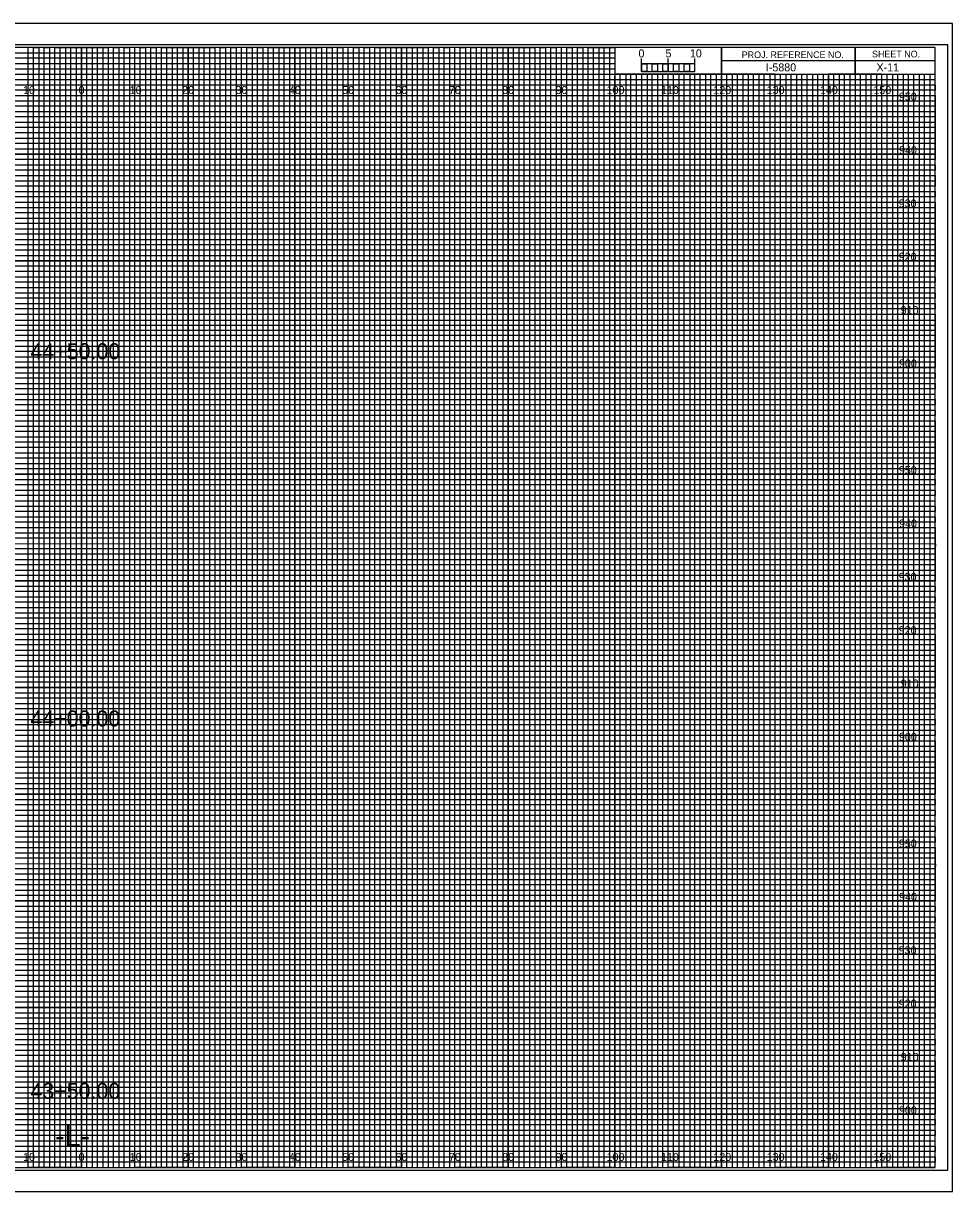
# Model space of a CAD drawing. Extents: x -13 to 323, y -4 to 3074.
# Drawn here: x 149.1 to 323.3, y 1975.5 to 2194.5 of the extents above; entities that cross this region are included whole.
import ezdxf

# ---------------------------------------------------------------- set-up
doc = ezdxf.new("R2010")
doc.units = 0
for name, color, linetype in [('Prop XS Alignment Label', 7, 'Continuous'), ('Prop XS Bar Scale Labels', 7, 'Continuous'), ('Prop XS Elevation Labels', 7, 'Continuous'), ('Prop XS Offset Labels', 7, 'Continuous'), ('Prop XS Project Number', 7, 'Continuous'), ('Prop XS Sheet Number', 7, 'Continuous'), ('Prop XS Station Labels', 7, 'Continuous'), ('Sheet Cross Section CELL', 7, 'Continuous'), ('Sheet Cross Section Grid Major CELL', 7, 'Continuous'), ('Sheet Cross Section Grid Middle CELL', 7, 'Continuous'), ('Sheet Cross Section Grid Minor 1 CELL', 7, 'Continuous'), ('Sheet Cross Section Grid Minor 2 CELL', 7, 'Continuous'), ('Sheet Cross Section Scale CELL', 7, 'Continuous'), ('Sheet Cutting Line CELL', 7, 'Continuous'), ('Sheet DOT Grid CELL', 7, 'Continuous'), ('Sheet Plot Border Inside CELL', 7, 'Continuous'), ('Sheet Plot Border Outside CELL', 7, 'Continuous')]:
    doc.layers.add(name, color=color, linetype=linetype)

msp = doc.modelspace()

# ---------------------------------------------------------------- linework, layer by layer
at = {"layer": 'Sheet Cross Section CELL'}
for p, q in [((305, 2190), (305, 2185)), ((305, 2185), (305, 2190)), ((280, 2187.5), (280, 2185)), ((320, 2187.49), (280, 2187.49)), ((280, 2185), (320, 2185))]:
    msp.add_line(p, q, dxfattribs=at)
for points in [[(320, 2190), (0, 2190), (0, 1980), (320, 1980)], [(280, 2190), (260, 2190), (260, 2185.03), (280, 2185.03)], [(320, 2190), (280, 2190), (280, 2185), (320, 2185)]]:
    msp.add_lwpolyline(points, close=True, dxfattribs=at)
at = {"layer": 'Sheet Cross Section Grid Major CELL'}
for p, q in [((150, 2190), (140, 2190)), ((150, 1980), (150, 2190)), ((170, 2190), (160, 2190)), ((160, 2190), (160, 1980)), ((170, 1980), (170, 2190)), ((190, 2190), (180, 2190)), ((180, 2190), (180, 1980)), ((190, 1980), (190, 2190)), ((210, 2190), (200, 2190)), ((200, 2190), (200, 1980)), ((210, 1980), (210, 2190)), ((230, 2190), (220, 2190)), ((220, 2190), (220, 1980)), ((230, 1980), (230, 2190)), ((250, 2190), (240, 2190)), ((240, 2190), (240, 1980)), ((250, 1980), (250, 2190)), ((260, 2190), (260, 1980)), ((270, 1980), (270, 2185)), ((290, 2185), (280, 2185)), ((280, 2185), (280, 1980)), ((290, 1980), (290, 2185)), ((310, 2185), (300, 2185)), ((300, 2185), (300, 1980)), ((310, 1980), (310, 2185)), ((160, 1980), (150, 1980)), ((180, 1980), (170, 1980)), ((200, 1980), (190, 1980)), ((220, 1980), (210, 1980)), ((240, 1980), (230, 1980)), ((260, 1980), (250, 1980)), ((280, 1980), (270, 1980)), ((300, 1980), (290, 1980)), ((320, 1980), (310, 1980)), ((320, 1980), (320, 1980))]:
    msp.add_line(p, q, dxfattribs=at)
for points in [[(0, 2180), (320, 2180), (320, 2170), (0, 2170)], [(0, 2160), (320, 2160), (320, 2150), (0, 2150)], [(0, 2140), (320, 2140), (320, 2130), (0, 2130)], [(0, 2120), (320, 2120), (320, 2110), (0, 2110)], [(0, 2100), (320, 2100), (320, 2090), (0, 2090)], [(0, 2080), (320, 2080), (320, 2070), (0, 2070)], [(0, 2060), (320, 2060), (320, 2050), (0, 2050)], [(0, 2040), (320, 2040), (320, 2030), (0, 2030)], [(0, 2020), (320, 2020), (320, 2010), (0, 2010)], [(0, 2000), (320, 2000), (320, 1990), (0, 1990)]]:
    msp.add_lwpolyline(points, dxfattribs=at)
at = {"layer": 'Sheet Cross Section Grid Middle CELL'}
for points in [[(145, 1980), (155, 1980), (155, 2190), (165, 2190), (165, 1980), (175, 1980), (175, 2190), (185, 2190), (185, 1980), (195, 1980), (195, 2190), (205, 2190), (205, 1980), (215, 1980), (215, 2190), (225, 2190), (225, 1980), (235, 1980), (235, 2190), (245, 2190), (245, 1980), (255, 1980), (255, 2190), (259.93, 2190), (260, 2190), (260, 2185), (264.99, 2185), (264.99, 1980), (275, 1980), (275, 2185), (285, 2185), (285, 1980), (295, 1980), (295, 2185), (305, 2185), (305, 1980), (315, 1980), (315, 2185)], [(0, 2185), (275, 2185)], [(0, 2165), (320, 2165), (320, 2175), (0, 2175)], [(0, 2145), (320, 2145), (320, 2155), (0, 2155)], [(0, 2125), (320, 2125), (320, 2135), (0, 2135)], [(0, 2105), (320, 2105), (320, 2115), (0, 2115)], [(0, 2085), (320, 2085), (320, 2095), (0, 2095)], [(0, 2065), (320, 2065), (320, 2075), (0, 2075)], [(0, 2045), (320, 2045), (320, 2055), (0, 2055)], [(0, 2025), (320, 2025), (320, 2035), (0, 2035)], [(0, 2005), (320, 2005), (320, 2015), (0, 2015)], [(0, 1985), (320, 1985), (320, 1995), (0, 1995)]]:
    msp.add_lwpolyline(points, dxfattribs=at)
at = {"layer": 'Sheet Cross Section Grid Minor 1 CELL'}
for p, q in [((0, 2189), (260, 2189)), ((260, 2187.98), (0, 2187.98)), ((260, 2189), (260, 2187.98)), ((0, 2187), (260, 2187)), ((260, 2185.89), (0, 2185.89)), ((260, 2187), (260, 2185.89)), ((0, 2184), (320, 2184))]:
    msp.add_line(p, q, dxfattribs=at)
for points in [[(0, 2183), (270, 2183), (320, 2183), (320, 2182), (0, 2182)], [(0, 2181), (320, 2181), (320, 2179), (0, 2179)], [(0, 2178), (320, 2178), (320, 2177), (0, 2176.98)], [(0, 2176), (320, 2176), (320, 2174), (0, 2174)], [(0, 2173), (320, 2173), (320, 2172), (0, 2172)], [(0, 2171), (320, 2171), (320, 2169), (0, 2169)], [(0, 2168), (320, 2168), (320, 2167), (0, 2167)], [(0, 2166), (320, 2166), (320, 2164), (0, 2164)], [(0, 2163), (320, 2163), (320, 2162), (0, 2162)], [(0, 2161), (320, 2161), (320, 2159), (0, 2159)], [(0, 2158), (320, 2158), (320, 2157), (0, 2157)], [(0, 2156), (320, 2156), (320, 2153.95), (320, 2153), (320, 2152), (0, 2152)], [(0, 2154), (320, 2154), (320, 2153), (0, 2153)], [(0, 2151), (320, 2151), (320, 2149), (0, 2149.03)], [(0, 2149.03), (320, 2149), (320, 2148), (0, 2148)], [(0, 2147), (320, 2147), (320, 2146), (0, 2146)], [(0, 2144), (320, 2144), (320, 2143), (0, 2143)], [(0, 2142), (320, 2142), (320, 2141), (0, 2141)], [(-0.07, 2138.89), (320, 2138.89), (320, 2137.88), (-0.07, 2137.88)], [(0, 2137), (320, 2137), (320, 2136), (0, 2136)], [(0, 2134), (320, 2134), (320, 2133), (0, 2133)], [(0, 2132), (320, 2132), (320, 2131), (0, 2131)], [(0, 2129), (320, 2129), (320, 2128), (0, 2128)], [(0, 2127), (320, 2127), (320, 2126), (0, 2126)], [(0, 2124), (320, 2124), (320, 2123), (0, 2123)], [(0, 2122), (320, 2122), (320, 2121), (0, 2121)], [(0, 2119), (320, 2119), (319.99, 2117.98), (0, 2118)], [(0, 2117), (320, 2117), (320, 2116), (0, 2116)], [(0, 2114), (320, 2114), (320, 2113), (0, 2113)], [(0, 2112), (320, 2112), (320, 2111), (0, 2111)], [(0, 2109), (320, 2109), (320, 2108), (0, 2108)], [(0, 2107), (320, 2107), (320, 2106), (0, 2106)], [(0, 2104), (320, 2104), (320, 2103), (0, 2103)], [(0, 2102), (320, 2102), (320, 2101), (0, 2101)], [(0, 2099), (320, 2099), (320, 2098), (0, 2098)], [(0, 2096.99), (320.07, 2096.91), (320, 2096), (0, 2096)], [(0, 2094), (320, 2094), (320, 2093), (0, 2093)], [(0, 2092), (320, 2092), (320, 2091), (0, 2091)], [(0, 2089), (320, 2089), (320, 2088), (0, 2088)], [(0, 2087), (320, 2087), (320, 2086), (0, 2086)], [(0, 2084), (320, 2084), (320, 2083), (0, 2083)], [(0, 2082), (320, 2082), (320, 2081), (0, 2081)], [(0, 2079), (320, 2079), (320, 2078), (0, 2078)], [(0, 2077), (320, 2077), (320, 2076), (0, 2076)], [(0, 2074), (320, 2074), (320, 2073), (0, 2073)], [(0, 2072), (320, 2072), (320, 2071), (0, 2071)], [(0, 2069), (320, 2069), (320, 2068), (0, 2068)], [(0, 2067), (320, 2067), (320, 2066), (0, 2066)], [(0, 2064), (320, 2064), (320, 2063), (0, 2063)], [(0, 2062), (320, 2062), (320, 2061), (0, 2061)], [(0, 2059), (320, 2059), (319.99, 2057.98), (0, 2058)], [(0, 2057), (320, 2057), (320, 2056), (0, 2056)], [(0, 2054), (320, 2054), (320, 2053), (0, 2053)], [(0, 2052), (320, 2052), (320, 2051), (0, 2051)], [(0, 2049), (320, 2049), (320, 2048), (0, 2048)], [(0, 2047), (320, 2047), (320, 2046), (0, 2046)], [(0, 2044), (320, 2044), (320, 2043), (0, 2043)], [(0, 2042), (320, 2042), (320, 2041), (0, 2041)], [(0, 2039), (320, 2039), (320, 2038), (0, 2038)], [(0, 2036.99), (320.07, 2036.91), (320, 2036), (0, 2036)], [(0, 2034), (320, 2034), (320, 2033), (0, 2033)], [(0, 2032), (320, 2032), (320, 2031), (0, 2031)], [(0, 2029), (320, 2029), (320, 2028), (0, 2028)], [(0, 2027), (320, 2027), (320, 2026), (0, 2026)], [(0, 2024), (320, 2024), (320, 2023), (0, 2023)], [(0, 2022), (320, 2022), (320, 2021), (0, 2021)], [(0, 2019), (320, 2019), (320, 2018), (0, 2018)], [(0, 2017), (320, 2017), (320, 2016), (0, 2016)], [(0, 2014), (320, 2014), (320, 2013), (0, 2013)], [(0, 2012), (320, 2012), (320, 2011), (0, 2011)], [(0, 2009), (320, 2009), (320, 2008), (0, 2008)], [(0, 2007), (320, 2007), (320, 2006), (0, 2006)], [(0, 2004), (320, 2004), (320, 2003), (0, 2003)], [(0, 2002), (320, 2002), (320, 2001), (0, 2001)], [(0, 1999), (320, 1999), (320, 1998), (0, 1998)], [(0, 1997), (320, 1997), (320, 1996), (0, 1996)], [(0, 1994), (320, 1994), (320, 1993), (0, 1993)], [(0, 1992), (320, 1992), (320, 1991), (0, 1991)], [(0, 1989), (320, 1989), (320, 1988), (0, 1988)], [(0, 1987), (320, 1987), (320, 1986), (0, 1986)], [(0, 1984), (320, 1984), (320, 1983), (0, 1983)], [(0, 1982), (320, 1982), (320, 1981), (0, 1981)]]:
    msp.add_lwpolyline(points, dxfattribs=at)
at = {"layer": 'Sheet Cross Section Grid Minor 2 CELL'}
for p, q in [((267, 2185), (266.01, 2185)), ((266.01, 2185), (266.01, 1980)), ((267, 1980), (267, 2185)), ((269, 2185), (268, 2185)), ((268, 2185), (268, 1980)), ((269, 1980), (269, 2185)), ((266.01, 1980), (265, 1980)), ((268, 1980), (267, 1980))]:
    msp.add_line(p, q, dxfattribs=at)
for points in [[(150, 1980), (151, 1980), (151, 2190), (152, 2190), (152, 1980)], [(152, 1980), (153, 1980), (153, 2190), (154, 2190), (154, 1980)], [(155, 1980), (156, 1980), (156, 2190), (157, 2190), (157, 1980)], [(157, 1980), (158, 1980), (158, 2190), (159, 2190), (159, 1980)], [(160, 1980), (161, 1980), (161, 2190), (162, 2190), (162, 1980)], [(162, 1980), (163, 1980), (163, 2190), (164, 2190), (164, 1980)], [(165, 1980), (166, 1980), (166, 2190), (167, 2190), (167, 1980)], [(167, 1980), (168, 1980), (168, 2190), (169, 2190), (169, 1980)], [(170, 1980), (171, 1980), (171, 2190), (172, 2190), (172, 1980)], [(172, 1980), (173, 1980), (173, 2190), (174, 2190), (174, 1980)], [(175, 1980), (176, 1980), (176, 2190), (177, 2190), (177, 1980)], [(177, 1980), (178, 1980), (178, 2190), (179, 2190), (179, 1980)], [(180, 1980), (181, 1980), (181, 2190), (182, 2190), (182, 1980)], [(182, 1980), (183, 1980), (183, 2190), (184, 2190), (184, 1980)], [(185, 1980), (186, 1980), (186, 2190), (187, 2190), (187, 1980)], [(187, 1980), (188, 1980), (188, 2190), (189, 2190), (189, 1980)], [(190, 1980), (191, 1980), (191, 2190), (192, 2190), (192, 1980)], [(192, 1980), (193, 1980), (193, 2190), (194, 2190), (194, 1980)], [(195, 1980), (196, 1980), (196, 2190), (197, 2190), (197, 1980)], [(197, 1980), (198, 1980), (198, 2190), (199, 2190), (199, 1980)], [(200, 1980), (201, 1980), (201, 2190), (202, 2190), (202, 1980)], [(202, 1980), (203, 1980), (203, 2190), (204, 2190), (204, 1980)], [(205, 1980), (206, 1980), (206, 2190), (207, 2190), (207, 1980)], [(207, 1980), (208, 1980), (208, 2190), (209, 2190), (209, 1980)], [(210, 1980), (211, 1980), (211, 2190), (212, 2190), (212, 1980)], [(212, 1980), (213, 1980), (213, 2190), (214, 2190), (214, 1980)], [(215, 1980), (216, 1980), (216, 2190), (217, 2190), (217, 1980)], [(217, 1980), (218, 1980), (218, 2190), (219, 2190), (219, 1980)], [(220, 1980), (221, 1980), (221, 2190), (222, 2190), (222, 1980)], [(222, 1980), (223, 1980), (223, 2190), (224, 2190), (224, 1980)], [(225, 1980), (226, 1980), (226, 2190), (227, 2190), (227, 1980)], [(227, 1980), (228, 1980), (228, 2190), (229, 2190), (229, 1980)], [(230, 1980), (231, 1980), (231, 2190), (232, 2190), (232, 1980)], [(232, 1980), (233, 1980), (233, 2190), (234, 2190), (234, 1980)], [(235, 1980), (236, 1980), (236, 2190), (237, 2190), (237, 1980)], [(237, 1980), (238, 1980), (238, 2190), (239, 2190), (239, 1980)], [(240, 1980), (241, 1980), (241, 2190), (242, 2190), (242, 1980)], [(242, 1980), (243, 1980), (243, 2190), (244, 2190), (244, 1980)], [(245, 1980), (246, 1980), (246, 2190), (247, 2190), (247, 1980)], [(247, 1980), (248, 1980), (248, 2190), (249, 2190), (249, 1980)], [(250, 1980), (251, 1980), (251, 2190), (252, 2190), (252, 1980)], [(252, 1980), (253, 1980), (253, 2190), (254, 2190), (254, 1980)], [(255, 1980), (256, 1980), (256, 2190), (257, 2190), (257, 1980)], [(257, 1980), (258, 1980), (258, 2190), (259, 2190), (259, 1980)], [(260, 1980), (261, 1980), (261, 2185), (262.02, 2185), (262.02, 1980)], [(262, 1980), (263, 1980), (263, 2185), (263.99, 2185), (263.99, 1980)], [(270, 1980), (270.98, 1980), (270.98, 2185), (272, 2185), (272, 1980)], [(272, 1980), (273, 1980), (273, 2185), (274.05, 2185), (274.05, 1980)], [(275, 1980), (276, 1980), (276, 2185), (277, 2185), (277, 1980)], [(277, 1980), (278, 1980), (278, 2185), (279, 2185), (279, 1980)], [(280, 1980), (281, 1980), (281, 2185), (282, 2185), (282, 1980)], [(282, 1980), (283, 1980), (283, 2185), (284, 2185), (284, 1980)], [(285, 1980), (286, 1980), (286, 2185), (287, 2185), (287, 1980)], [(287, 1980), (288, 1980), (288, 2185), (289, 2185), (289, 1980)], [(290, 1980), (291, 1980), (291, 2185), (292, 2185), (292, 1980)], [(292, 1980), (293, 1980), (293, 2185), (294, 2185), (294, 1980)], [(295, 1980), (296, 1980), (296, 2185), (297, 2185), (297, 1980)], [(297, 1980), (298, 1980), (298, 2185), (299, 2185), (299, 1980)], [(300, 1980), (301, 1980), (301, 2185), (302, 2185), (302, 1980)], [(302, 1980), (303, 1980), (303, 2185), (304, 2185), (304, 1980)], [(305, 1980), (306, 1980), (306, 2185), (307, 2185), (307, 1980)], [(307, 1980), (308, 1980), (308, 2185), (309, 2185), (309, 1980)], [(310, 1980), (311, 1980), (311, 2185), (312, 2185), (312, 1980)], [(312, 1980), (313, 1980), (313, 2185), (314, 2185), (314, 1980)], [(315, 1980), (316, 1980), (316, 2185), (317, 2185), (317, 1980)], [(317, 1980), (318, 1980), (318, 2185), (319, 2185), (319, 1980)]]:
    msp.add_lwpolyline(points, dxfattribs=at)
at = {"layer": 'Sheet Cross Section Scale CELL'}
for p, q in [((265, 2185.49), (265, 2187.9)), ((265, 2186.9), (265, 2187.9)), ((270, 2185.49), (270, 2187.9)), ((275, 2185.49), (275, 2187.9)), ((275, 2186.9), (275, 2187.9))]:
    msp.add_line(p, q, dxfattribs=at)
for points in [[(275, 2186.9), (265, 2186.9), (265, 2185.49), (275, 2185.49)], [(265, 2186.9), (266, 2186.9), (266, 2185.49), (265, 2185.49)], [(267, 2186.9), (268, 2186.9), (268, 2185.49), (267, 2185.49)], [(269, 2186.9), (270, 2186.9), (270, 2185.49), (269, 2185.49)], [(271, 2186.9), (272, 2186.9), (272, 2185.49), (271, 2185.49)], [(273, 2186.9), (274, 2186.9), (274, 2185.49), (273, 2185.49)]]:
    msp.add_lwpolyline(points, close=True, dxfattribs=at)
at = {"layer": 'Sheet Cutting Line CELL'}
for p, q in [((323.3, 2194.5), (-13.4, 2194.5)), ((-13.4, 1975.5), (323.3, 1975.5))]:
    msp.add_line(p, q, dxfattribs=at)
at = {"layer": 'Sheet DOT Grid CELL'}
for p, q in [((150, 1980), (150, 2190)), ((160, 1980), (160, 2190)), ((170, 1980), (170, 2190)), ((180, 1980), (180, 2190)), ((190, 1980), (190, 2190)), ((200, 1980), (200, 2190)), ((210, 1980), (210, 2190)), ((220, 1980), (220, 2190)), ((230, 1980), (230, 2190)), ((240, 1980), (240, 2190)), ((250, 1980), (250, 2190)), ((260, 1980), (260, 2184.69)), ((270, 1980), (270, 2184.69)), ((280, 1980), (280, 2184.69)), ((290, 1980), (290, 2184.69)), ((300, 1980), (300, 2184.69)), ((310, 1980), (310, 2184.69)), ((0, 2180), (320, 2180)), ((0, 2170), (320, 2170)), ((0, 2160), (320, 2160)), ((0, 2150), (320, 2150)), ((0, 2140), (320, 2140)), ((0, 2130), (320, 2130)), ((0, 2120), (320, 2120)), ((0, 2110), (320, 2110)), ((0, 2100), (320, 2100)), ((0, 2090), (320, 2090)), ((0, 2080), (320, 2080)), ((0, 2070), (320, 2070)), ((0, 2060), (320, 2060)), ((0, 2050), (320, 2050)), ((0, 2040), (320, 2040)), ((0, 2030), (320, 2030)), ((0, 2020), (320, 2020)), ((0, 2010), (320, 2010)), ((0, 2000), (320, 2000)), ((0, 1990), (320, 1990))]:
    msp.add_line(p, q, dxfattribs=at)
at = {"layer": 'Sheet Plot Border Inside CELL'}
msp.add_lwpolyline([(-10.8, 1979.5), (322.4, 1979.5), (322.4, 2190.5), (-10.8, 2190.5)], close=True, dxfattribs=at)
at = {"layer": 'Sheet Plot Border Outside CELL'}
msp.add_lwpolyline([(-13.4, 1975.5), (323.3, 1975.5), (323.3, 2194.5), (-13.4, 2194.5)], close=True, dxfattribs=at)

# ---------------------------------------------------------------- texts
at = {"layer": 'Prop XS Alignment Label'}
msp.add_text('-L-', height=4, dxfattribs=at).set_placement((155.06, 1984))
at = {"layer": 'Prop XS Bar Scale Labels'}
for s, p in [('5', (269.47, 2188.12)), ('10', (274.04, 2188.12))]:
    msp.add_text(s, height=1.5, dxfattribs=at).set_placement(p)
at = {"layer": 'Prop XS Elevation Labels'}
for s, p in [('950', (313.22, 2180)), ('940', (313.26, 2170)), ('930', (313.18, 2160)), ('920', (313.19, 2150)), ('910', (313.57, 2140)), ('900', (313.24, 2130)), ('950', (313.22, 2110)), ('940', (313.26, 2100)), ('930', (313.18, 2090)), ('920', (313.19, 2080)), ('910', (313.57, 2070)), ('900', (313.24, 2060)), ('950', (313.22, 2040)), ('940', (313.26, 2030)), ('930', (313.18, 2020)), ('920', (313.19, 2010)), ('910', (313.57, 2000)), ('900', (313.24, 1990))]:
    msp.add_text(s, height=1.5, dxfattribs=at).set_placement(p)
at = {"layer": 'Prop XS Offset Labels'}
for s, p in [('10', (149.04, 2181.25)), ('0', (159.45, 2181.25)), ('0', (159.45, 2181.25)), ('10', (169.04, 2181.25)), ('20', (178.86, 2181.25)), ('30', (188.86, 2181.25)), ('40', (198.86, 2181.25)), ('50', (208.86, 2181.25)), ('60', (218.86, 2181.25)), ('70', (228.86, 2181.25)), ('80', (238.86, 2181.25)), ('90', (248.86, 2181.25)), ('100', (258.44, 2181.25)), ('110', (268.62, 2181.25)), ('120', (278.44, 2181.25)), ('130', (288.44, 2181.25)), ('140', (298.44, 2181.25)), ('150', (308.44, 2181.25)), ('10', (149.04, 1981.25)), ('0', (159.45, 1981.25)), ('0', (159.45, 1981.25)), ('10', (169.04, 1981.25)), ('20', (178.86, 1981.25)), ('30', (188.86, 1981.25)), ('40', (198.86, 1981.25)), ('50', (208.86, 1981.25)), ('60', (218.86, 1981.25)), ('70', (228.86, 1981.25)), ('80', (238.86, 1981.25)), ('90', (248.86, 1981.25)), ('100', (258.44, 1981.25)), ('110', (268.62, 1981.25)), ('120', (278.44, 1981.25)), ('130', (288.44, 1981.25)), ('140', (298.44, 1981.25)), ('150', (308.44, 1981.25))]:
    msp.add_text(s, height=1.5, dxfattribs=at).set_placement(p)
at = {"layer": 'Prop XS Project Number'}
msp.add_text('I-5880', height=1.5, dxfattribs=at).set_placement((288.28, 2185.5))
at = {"layer": 'Prop XS Sheet Number'}
msp.add_text('X-11', height=1.5, dxfattribs=at).set_placement((309.02, 2185.5))
at = {"layer": 'Prop XS Station Labels'}
for s, p in [('44+50.00', (150.41, 2131.54)), ('44+00.00', (150.41, 2062.7)), ('43+50.00', (150.41, 1992.88))]:
    msp.add_text(s, height=3, dxfattribs=at).set_placement(p)
at = {"layer": 'Sheet Cross Section CELL'}
for s, p in [('PROJ. REFERENCE NO.', (283.77, 2187.99)), ('SHEET NO.', (308.19, 2188.12))]:
    msp.add_text(s, height=1.25, dxfattribs=at).set_placement(p)
at = {"layer": 'Sheet Cross Section Scale CELL'}
msp.add_text('0', height=1.5, dxfattribs=at).set_placement((264.41, 2188.12))

doc.saveas('drawing.dxf')
